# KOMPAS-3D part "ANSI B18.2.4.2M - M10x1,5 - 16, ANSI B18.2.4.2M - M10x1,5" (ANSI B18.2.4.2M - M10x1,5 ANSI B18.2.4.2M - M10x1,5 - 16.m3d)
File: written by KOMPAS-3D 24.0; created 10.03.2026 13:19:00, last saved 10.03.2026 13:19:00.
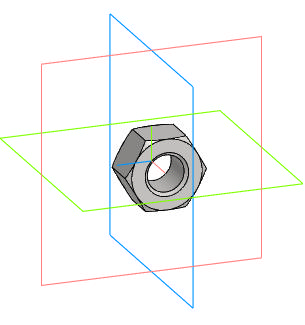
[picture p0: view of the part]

Document properties: Автор: R2D2; Полное имя файла: E:\Работа\Зайцев\BV3232P(4pc)-FP-3WL-F-ISO-H Кран шаровой DN.ru Ду15-100 Ру16\DN100\исходные материалы\ANSI B18.2.4.2M - M10x1,5 ANSI B18.2.4.2M - M10x1,5 - 16.m3d

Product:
- Body: Solid1  | qty 1
- Part/product: ANSI B18.2.4.2M - M10x1,5 - 16  | designation ANSI B18.2.4.2M - M10x1,5
    Комментарий: Типы метрических   шестигранных гаек   2
    additional columns: Сталь, мягкая

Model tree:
1. Solid1  (labels: Solid1)

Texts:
  ANSI B18.2.4.2M - M10x1,5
